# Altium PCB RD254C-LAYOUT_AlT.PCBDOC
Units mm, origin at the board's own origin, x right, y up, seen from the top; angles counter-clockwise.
Board outline 100 x 100 mm, 2 copper layers (TOP, BOTTOM), stack 0 mm thick; 40 components, 28 nets, 265 pads, 0 vias.
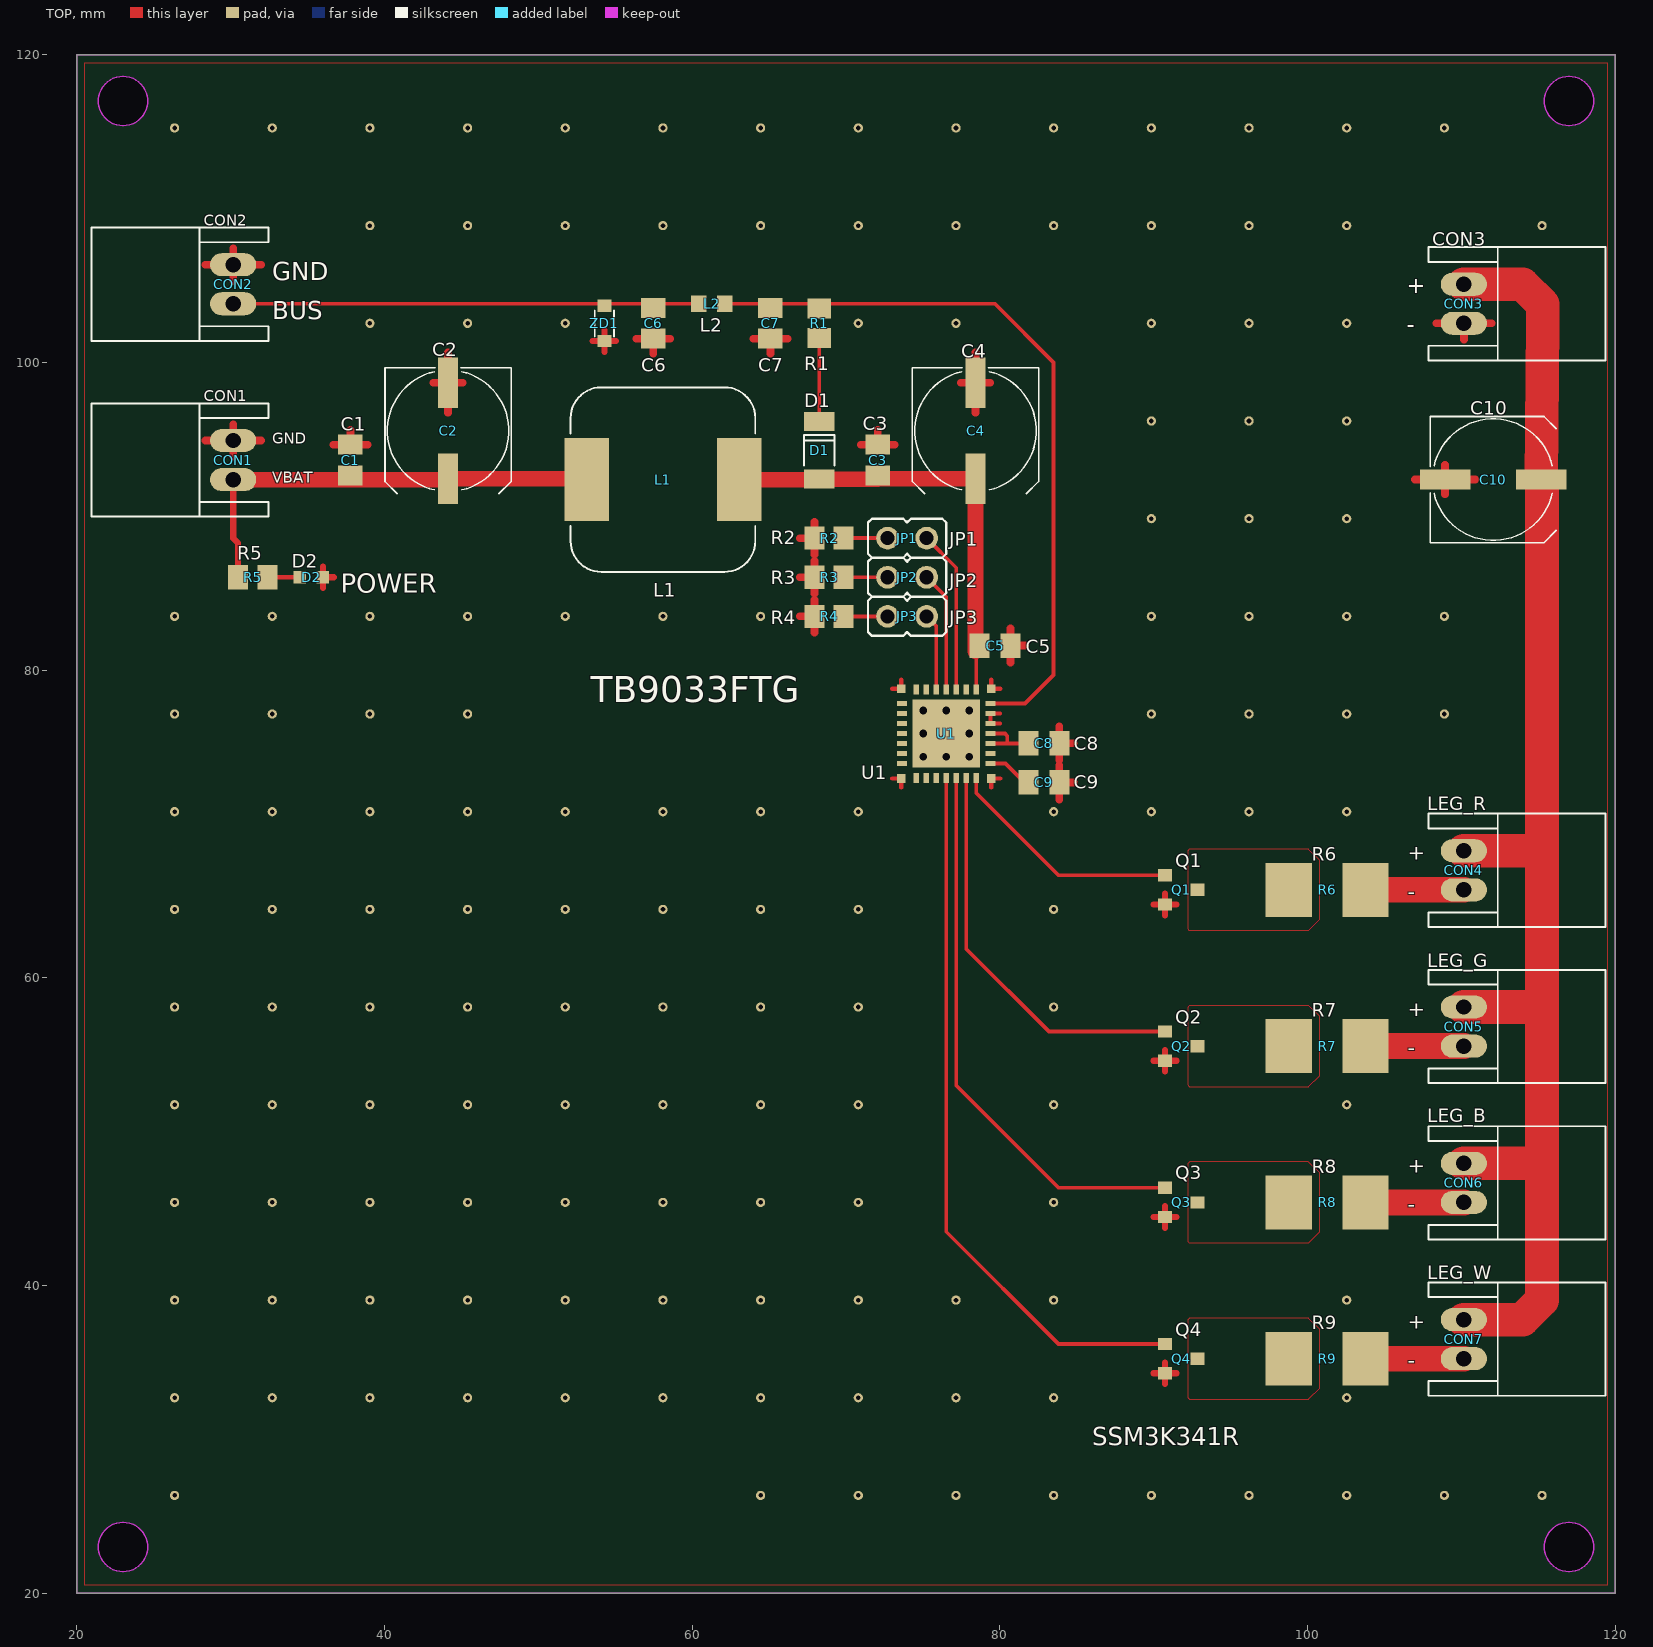
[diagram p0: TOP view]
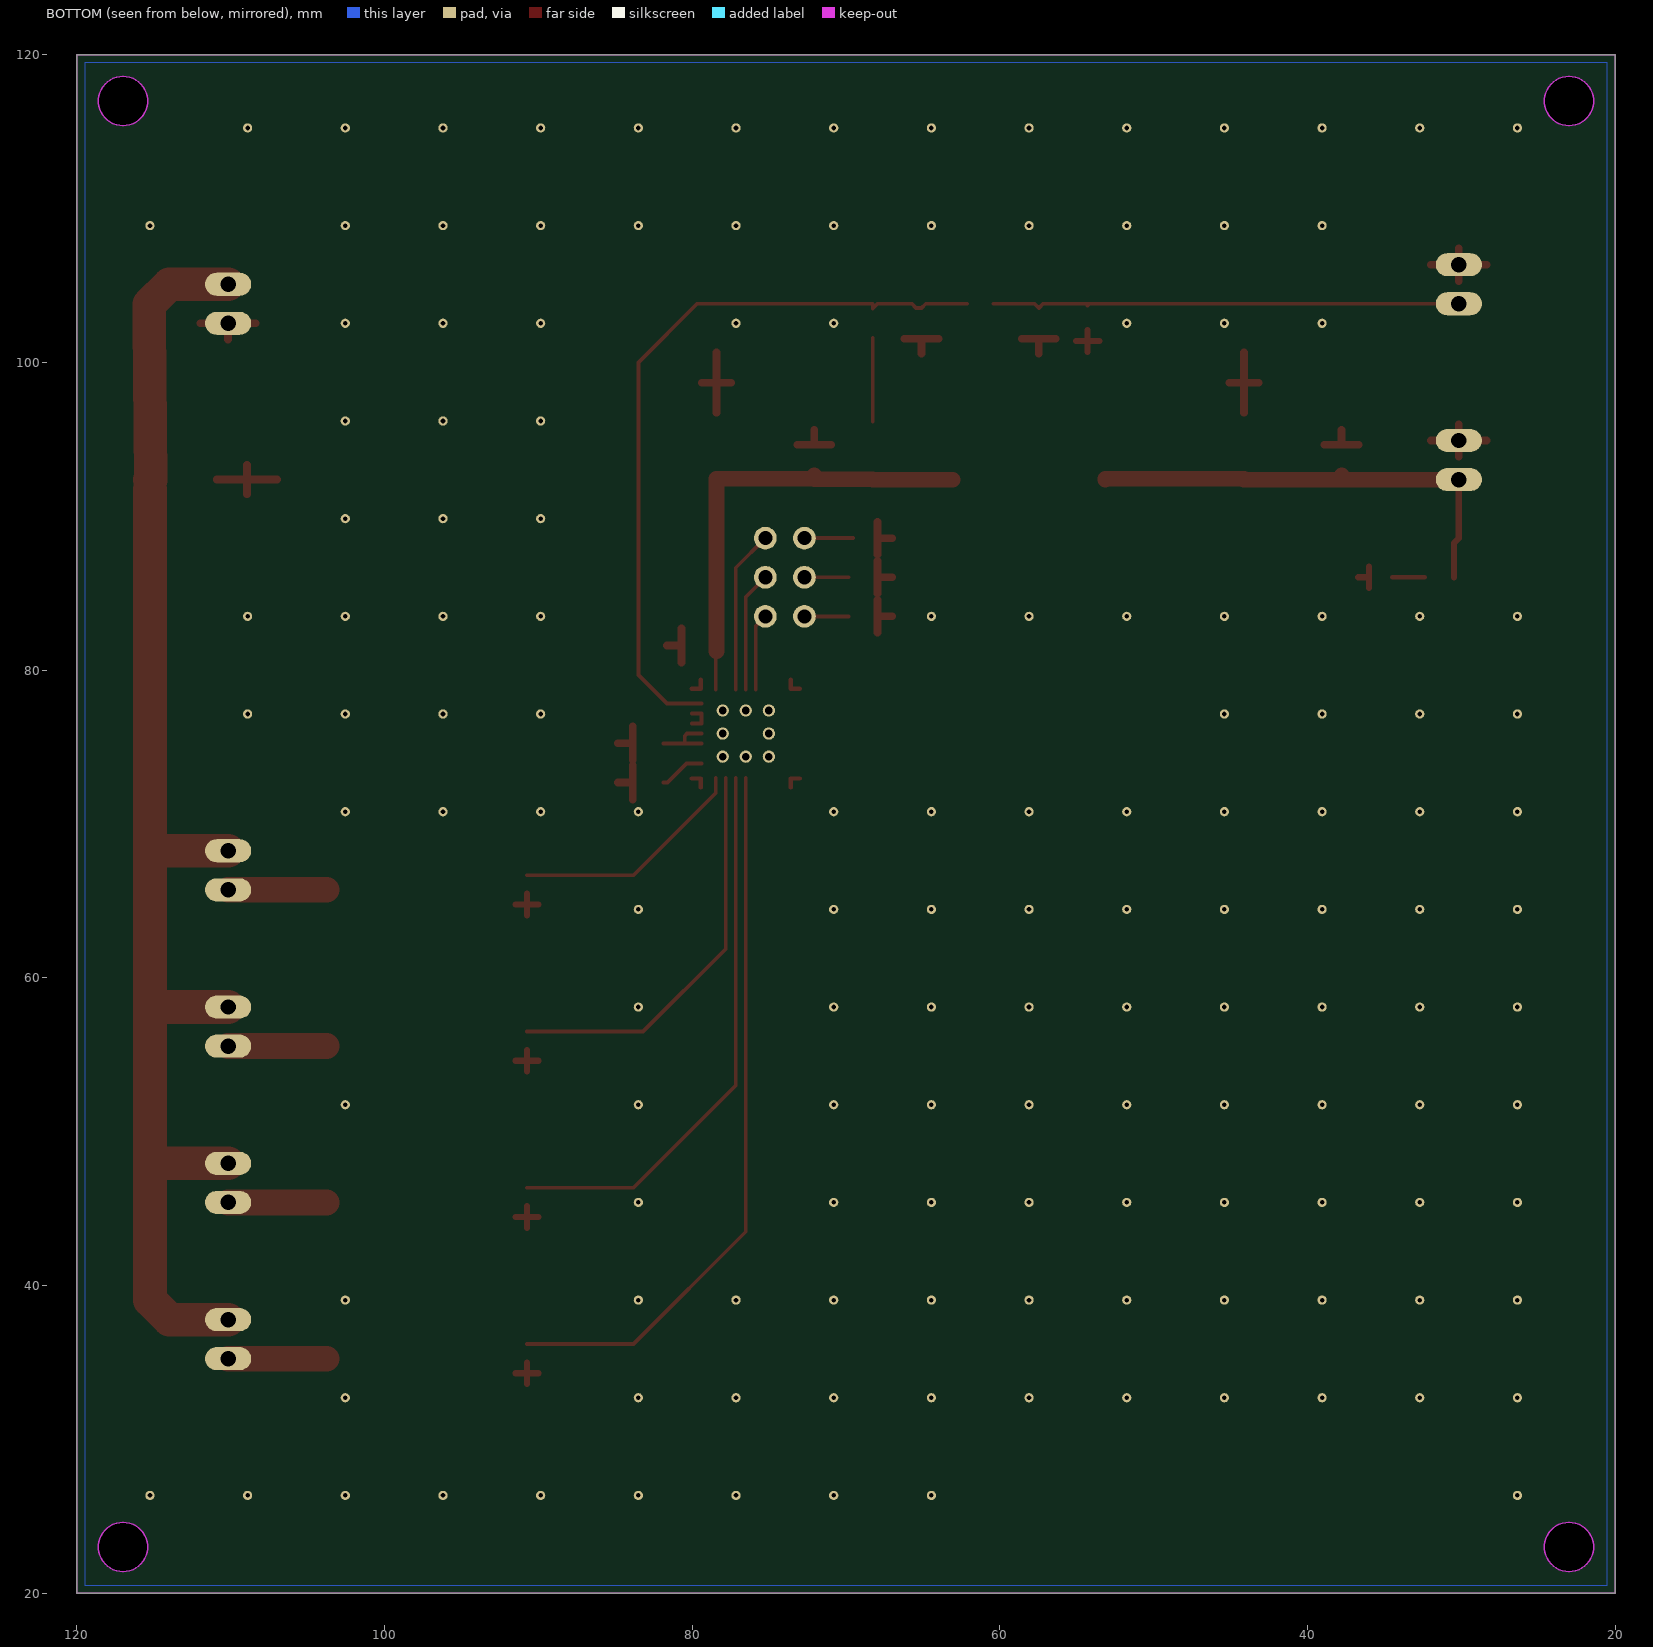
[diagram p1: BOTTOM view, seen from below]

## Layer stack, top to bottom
Top Solder: solder mask 0.0102, Solder Resist, Dk 3.5
TOP: signal copper (thickness not stored)
BOTTOM: signal copper (thickness not stored)
Bottom Solder: solder mask 0.0102, Solder Resist, Dk 3.5

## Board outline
20,20 20,120 120,120 120,20

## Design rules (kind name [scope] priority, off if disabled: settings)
AssemblyTestPointUsage [All] p0: scope1count=1 scope1_0_kind=Board scope1_0_value=Board scope2count=1 scope2_0_kind=Board scope2_0_value=Board commentlength=0
AssemblyTestpoint [All] p0: scope1count=1 scope1_0_kind=Board scope1_0_value=Board scope2count=1 scope2_0_kind=Board scope2_0_value=Board commentlength=0
Clearance [All] p0: scope1count=1 scope1_0_kind=Board scope1_0_value=Board scope2count=1 scope2_0_kind=Board scope2_0_value=Board commentlength=0 gap=0.254
Clearance [All] p1: gap=0.254 ignorepadtopadclearanceinfootprint=TRUE except(0: Arc-Arc Arc-Track Arc-Text Track-Track Track-Text Text-Text; 0.3: Arc-Hole Track-Hole SMDPad-Hole THPad-Hole Via-Hole Fill-Hole Poly-Hole Region-Hole Text-Hole)
ComponentClearance [All] p0: scope1count=1 scope1_0_kind=Board scope1_0_value=Board scope2count=1 scope2_0_kind=Board scope2_0_value=Board commentlength=0 gap=0.254 collisioncheckmode=3
DiffPairsRouting [All] p0: scope1count=1 scope1_0_kind=Board scope1_0_value=Board scope2count=1 scope2_0_kind=Board scope2_0_value=Board commentlength=0
FabricationTestPointUsage [All] p0: scope1count=1 scope1_0_kind=Board scope1_0_value=Board scope2count=1 scope2_0_kind=Board scope2_0_value=Board commentlength=0 valid=0 allowmultiple=FALSE
FabricationTestpoint [All] p0: scope1count=1 scope1_0_kind=Board scope1_0_value=Board scope2count=1 scope2_0_kind=Board scope2_0_value=Board commentlength=0 side=3 testpointundercomponent=TRUE minsize=1.016 maxsize=2.54 preferedsize=1.524 minholesize=0 maxholesize=1.016 preferedholesize=0.813 testpointgrid=0.025
FanoutControl Fanout_BGA [All] p0 off: scope1count=1 scope1_0_kind=Board scope1_0_value=Board scope2count=1 scope2_0_kind=Board scope2_0_value=Board commentlength=69 // Protel DXP Scope 1 Expression Was: IsBGA   Fanout_BGA (Default Rule)
FanoutControl Fanout_LCC [All] p0 off: scope1count=1 scope1_0_kind=Board scope1_0_value=Board scope2count=1 scope2_0_kind=Board scope2_0_value=Board commentlength=69 // Protel DXP Scope 1 Expression Was: IsLCC   Fanout_LCC (Default Rule)
FanoutControl Fanout_SOIC [All] p0 off: scope1count=1 scope1_0_kind=Board scope1_0_value=Board scope2count=1 scope2_0_kind=Board scope2_0_value=Board commentlength=71 // Protel DXP Scope 1 Expression Was: IsSOIC   Fanout_SOIC (Default Rule)
FanoutControl Fanout_Small [All] p0 off: scope1count=1 scope1_0_kind=Board scope1_0_value=Board scope2count=1 scope2_0_kind=Board scope2_0_value=Board commentlength=84 // Protel DXP Scope 1 Expression Was: (CompPinCount < 5)   Fanout_Small (Default Rule)
FanoutControl Fanout_Default [All] p0: scope1count=1 scope1_0_kind=Board scope1_0_value=Board scope2count=1 scope2_0_kind=Board scope2_0_value=Board commentlength=30 // Fanout_Default (Default Rule)
Height [All] p0: scope1count=1 scope1_0_kind=Board scope1_0_value=Board scope2count=1 scope2_0_kind=Board scope2_0_value=Board commentlength=0
HoleSize [All] p0: scope1count=1 scope1_0_kind=Board scope1_0_value=Board scope2count=1 scope2_0_kind=Board scope2_0_value=Board commentlength=0 absolutevalues=TRUE maxlimit=100 minlimit=0.001 maxpercent=80.000 minpercent=20.000
HoleSize [All] p1: absolutevalues=TRUE maxlimit=100 minlimit=0.001 maxpercent=80.000 minpercent=20.000
HoleToHoleClearance [All] p0: scope1count=1 scope1_0_kind=Board scope1_0_value=Board scope2count=1 scope2_0_kind=Board scope2_0_value=Board commentlength=0
HoleToHoleClearance [All] p1: gap=0.4 allowstackedmicrovias=FALSE
LayerPairs [All] p0: scope1count=1 scope1_0_kind=Board scope1_0_value=Board scope2count=1 scope2_0_kind=Board scope2_0_value=Board commentlength=0 enforce=TRUE
MinimumSolderMaskSliver [All] p0: scope1count=1 scope1_0_kind=Board scope1_0_value=Board scope2count=1 scope2_0_kind=Board scope2_0_value=Board commentlength=0
MinimumSolderMaskSliver [All] p1: minsoldermaskwidth=0.1
NetAntennae [All] p0: scope1count=1 scope1_0_kind=Board scope1_0_value=Board scope2count=1 scope2_0_kind=Board scope2_0_value=Board commentlength=0
NetAntennae [All] p1: netantennaetolerance=100
PasteMaskExpansion [All] p0: scope1count=1 scope1_0_kind=Board scope1_0_value=Board scope2count=1 scope2_0_kind=Board scope2_0_value=Board commentlength=0 expansion=0
PlaneClearance [All] p0: scope1count=1 scope1_0_kind=Board scope1_0_value=Board scope2count=1 scope2_0_kind=Board scope2_0_value=Board commentlength=0 clearance=0.001
PlaneClearance [All] p1: clearance=0.001
PlaneConnect [All] p0: scope1count=1 scope1_0_kind=Board scope1_0_value=Board scope2count=1 scope2_0_kind=Board scope2_0_value=Board commentlength=0 planeconnectstyle=Direct reliefexpansion=0.508 reliefentries=4 reliefconductorwidth=0.254 reliefairgap=0.254
PlaneConnect [All] p1: planeconnectstyle=Direct reliefexpansion=0.508 reliefentries=4 reliefconductorwidth=0.254 reliefairgap=0.254
PolygonConnect [All] p0: scope1count=1 scope1_0_kind=Board scope1_0_value=Board scope2count=1 scope2_0_kind=Board scope2_0_value=Board commentlength=0 connectstyle=Direct reliefconductorwidth=0.254 reliefentries=4 polygonreliefangle="90 Angle"
PolygonConnect [All] p1: connectstyle=Direct reliefconductorwidth=0.254 reliefentries=4 polygonreliefangle="90 Angle" airgapwidth=0.254
RoutingCorners [All] p0: scope1count=1 scope1_0_kind=Board scope1_0_value=Board scope2count=1 scope2_0_kind=Board scope2_0_value=Board commentlength=0 cornerstyle=45-Degree minsetback=2.54 maxsetback=2.54
RoutingLayers [All] p0: scope1count=1 scope1_0_kind=Board scope1_0_value=Board scope2count=1 scope2_0_kind=Board scope2_0_value=Board commentlength=0 top layer=Automatic bottom layer=Automatic
RoutingPriority [All] p0: scope1count=1 scope1_0_kind=Board scope1_0_value=Board scope2count=1 scope2_0_kind=Board scope2_0_value=Board commentlength=0
RoutingTopology [All] p0: scope1count=1 scope1_0_kind=Board scope1_0_value=Board scope2count=1 scope2_0_kind=Board scope2_0_value=Board commentlength=0 topology=Shortest
RoutingVias [All] p0: scope1count=1 scope1_0_kind=Board scope1_0_value=Board scope2count=1 scope2_0_kind=Board scope2_0_value=Board commentlength=0 holewidth=0.1 width=0.1 viastyle="Through Hole" minholewidth=0.001 minwidth=0.001 maxholewidth=100 maxwidth=100
RoutingVias [All] p1: holewidth=0.1 width=0.1 viastyle="Through Hole" minholewidth=0.001 minwidth=0.001 maxholewidth=100 maxwidth=100
ShortCircuit [All] p0: scope1count=1 scope1_0_kind=Board scope1_0_value=Board scope2count=1 scope2_0_kind=Board scope2_0_value=Board commentlength=0 allowed=FALSE
SilkToBoardRegionClearance [All] p0: scope1count=1 scope1_0_kind=Board scope1_0_value=Board scope2count=1 scope2_0_kind=Board scope2_0_value=Board commentlength=0
SilkToSilkClearance [All] p0: scope1count=1 scope1_0_kind=Board scope1_0_value=Board scope2count=1 scope2_0_kind=Board scope2_0_value=Board commentlength=0
SilkToSilkClearance [All] p1: silktosilkclearance=0.001
SilkToSolderMaskClearance [All] p0 off: scope1count=1 scope1_0_kind=Board scope1_0_value=Board scope2count=1 scope2_0_kind=Board scope2_0_value=Board commentlength=44 // Protel DXP Scope 1 Expression Was: IsPad
SilkToSolderMaskClearance [IsPad] p1: minsilkscreentomaskgap=0 clearancetoexposedcopper=TRUE
SolderMaskExpansion [All] p0: scope1count=1 scope1_0_kind=Board scope1_0_value=Board scope2count=1 scope2_0_kind=Board scope2_0_value=Board commentlength=0 expansion=0.001
SolderMaskExpansion [All] p1: expansion=0.001
UnRoutedNet [All] p0: scope1count=1 scope1_0_kind=Board scope1_0_value=Board scope2count=1 scope2_0_kind=Board scope2_0_value=Board commentlength=0
UnpouredPolygon [All] p0: scope1count=1 scope1_0_kind=Board scope1_0_value=Board scope2count=1 scope2_0_kind=Board scope2_0_value=Board commentlength=0
Width [All] p0: scope1count=1 scope1_0_kind=Board scope1_0_value=Board scope2count=1 scope2_0_kind=Board scope2_0_value=Board commentlength=0 maxlimit=1000 minlimit=2539.975 preferedwidth=0
Width [All] p1: maxlimit=1000 minlimit=2539.975 preferedwidth=0 toplayer_minwidth=0 bottomlayer_minwidth=0 minimp=50.000000 maximp=50.000000 favimp=50.000000
22 further rules are at their usual default settings.

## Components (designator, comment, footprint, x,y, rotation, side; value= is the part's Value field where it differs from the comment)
C1 "C0805K" C0805K 37.78,93.66 r90 top
C2 "UD-8X10_NICHICON_01" UD-8X10_NICHICON_01 44.13,95.565 r270 top
C3 "C0805K" C0805K 72.07,93.66 r90 top
C4 "UD-8X10_NICHICON_01" UD-8X10_NICHICON_01 78.42,95.565 r270 top
C5 "C0805K" C0805K 79.69,81.595 r0 top
C6 "C0805K" C0805K 57.465,102.55 r270 top
C7 "C0805K" C0805K 65.085,102.55 r270 top
C8 "C0805K" C0805K 82.865,75.245 r180 top
C9 "C0805K" C0805K 82.865,72.705 r180 top
C10 "UD-8X10_NICHICON_01" UD-8X10_NICHICON_01 112.075,92.39 r0 top
cam1 "A4L-LOC" A4L-LOC -51,-27 r0 top
CON1 "S2B-XH-A" S2B-XH-A 30.16,93.66 r90 top
CON2 "S2B-XH-A" S2B-XH-A 30.16,105.09 r90 top
CON3 "S2B-XH-A" S2B-XH-A 110.17,103.82 r270 top
CON4 "S2B-XH-A" S2B-XH-A 110.17,66.99 r270 top
CON5 "S2B-XH-A" S2B-XH-A 110.17,56.83 r270 top
CON6 "S2B-XH-A" S2B-XH-A 110.17,46.67 r270 top
CON7 "S2B-XH-A" S2B-XH-A 110.17,36.51 r270 top
D1 "LL4148" LL4148 68.26,94.295 r90 top
D2 "CHIP-LED0603" CHIP-LED0603 35.24,86.04 r270 top
JP1 "JP1" JP1 73.975,88.58 r270 top
JP2 "JP1" JP1 73.975,86.04 r270 top
JP3 "JP1" JP1 73.975,83.5 r270 top
L1 "7447709222" 7447709222 58.1,92.39 r270 top
L2 "R0603" R0603 61.275,103.82 r0 top
Q1 "SOT-23F" SOT-23F 92.39,65.72 r270 top
Q2 "SOT-23F" SOT-23F 92.39,55.56 r270 top
Q3 "SOT-23F" SOT-23F 92.39,45.4 r270 top
Q4 "SOT-23F" SOT-23F 92.39,35.24 r270 top
R1 "R0805" R0805 68.26,102.55 r270 top
R2 "R0805" R0805 68.895,88.58 r180 top
R3 "R0805" R0805 68.895,86.04 r180 top
R4 "R0805" R0805 68.895,83.5 r180 top
R5 "M0805" M0805 31.43,86.04 r180 top
R6 "R2512-2010" R2512-2010 101.28,65.72 r0 top
R7 "R2512-2010" R2512-2010 101.28,55.56 r0 top
R8 "R2512-2010" R2512-2010 101.28,45.4 r0 top
R9 "R2512-2010" R2512-2010 101.28,35.24 r0 top
U1 "P-VQFN28-0606-0_65-003_01" P-VQFN28-0606-0_65-003_01 76.515,75.88 r180 top
ZD1 "USC" USC 54.29,102.55 r270 top

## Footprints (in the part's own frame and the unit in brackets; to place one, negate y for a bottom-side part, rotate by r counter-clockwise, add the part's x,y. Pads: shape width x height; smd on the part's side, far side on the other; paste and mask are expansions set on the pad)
7447709222 [mm] "KC00080BKP"
  rect 5.4x2.9 smd paste-5.603 mask+0: 1(0,-4.95) 2(0,4.95)
  silkscreen extent -6,-6 6,6
A4L-LOC [mm] "KC00080BKP"
C0805K [mm] "KC00080BKP"
  rect 1.3x1.6 smd paste-1.803 mask+0: 1(-1,0) 2(1,0)
CHIP-LED0603 [mm] "KC00080BKP"
  rect 0.8x0.8 smd paste-1.003 mask+0: A(0,-0.75) C(0,0.75)
JP1 [mm] "KC00080BKP"
  round 1.48 / inner round 0 / far side round 1.48 hole 0.914 paste-1.68 mask+0: 1(0,-1.27) 2(0,1.27)
  silkscreen extent -1.27,-2.54 1.27,2.54
LL4148 [mm] "KC00080BKP"
  rect 1.25x2 smd paste-2.203 mask+0: A(-1.875,0) K(1.875,0)
  silkscreen extent -1,-1 1,1
M0805 [mm] "KC00080BKP"
  rect 1.3x1.6 smd paste-1.803 mask+0: 1(-0.95,0) 2(0.95,0)
P-VQFN28-0606-0_65-003_01 [mm] "KC00080BKP"
  rect 0.35x0.65 smd paste-0.853 mask+0: 1(-1.95,-2.875) 2(-1.3,-2.875) 3(-0.65,-2.875) 4(0,-2.875) 5(0.65,-2.875) 6(1.3,-2.875) 7(1.95,-2.875) 15(1.95,2.875) 16(1.3,2.875) 17(0.65,2.875) 18(0,2.875) 19(-0.65,2.875) 20(-1.3,2.875) 21(-1.95,2.875)
  rect 0.56x0.56 smd paste-0.763 mask+0: 1T(-2.92,-2.92) 2T(2.92,-2.92) 3T(2.92,2.92) 4T(-2.92,2.92)
  rect 0.65x0.35 smd paste-0.853 mask+0: 8(2.875,-1.95) 9(2.875,-1.3) 10(2.875,-0.65) 11(2.875,0) 12(2.875,0.65) 13(2.875,1.3) 14(2.875,1.95) 22(-2.875,1.95) 23(-2.875,1.3) 24(-2.875,0.65) 25(-2.875,0) 26(-2.875,-0.65) 27(-2.875,-1.3) 28(-2.875,-1.95)
  rect 4.4x4.4 smd paste-4.603 mask+0: E_PAD(0,0)
  round 0.8 / inner round 0 / far side round 0.8 hole 0.5 paste-1.05 mask+0: ""(-1.5,1.5) ""(-1.5,0) ""(-1.5,-1.5) ""(0,1.5) ""(0,-1.5) ""(1.5,1.5) ""(1.5,0) ""(1.5,-1.5)
R0603 [mm] "KC00080BKP"
  rect 1x1.1 smd paste-1.303 mask+0: 1(-0.85,0) 2(0.85,0)
R0805 [mm] "KC00080BKP"
  rect 1.3x1.5 smd paste-1.703 mask+0: 1(-0.95,0) 2(0.95,0)
R2512-2010 [mm] "KC00080BKP"
  rect 3x3.5 smd paste-3.703 mask+0: P_1(-2.5,0) P_2(2.5,0)
S2B-XH-A [mm] "KC00080BKP"
  oval 1.5x3 / inner round 0 / far side oval 1.5x3 hole 1 paste-3.203 mask+0: 1(1.27,0) 2(-1.27,0)
  silkscreen extent -3.68,-2.3 3.68,9.2
SOT-23F [mm] "KC00080BKP"
  rect 0.8x0.9 smd paste-1.103 mask+0: 1(-0.95,-1.65) 2(0.95,-1.65) 3(0,0.45)
UD-8X10_NICHICON_01 [mm] "KC00080BKP"
  rect 3.3x1.3 smd paste-3.503 mask+0: 1(-3.125,0) 2(3.125,0)
  silkscreen extent -4.1,-4.1 4.1,4.1
USC [mm] "KC00080BKP"
  rect 0.8x0.9 smd paste-1.103 mask+0: 1(-1.15,0) 2(1.15,0)
  silkscreen extent -0.85,-0.63 0.85,0.63

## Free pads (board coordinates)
  round 0 hole 3.2 unplated paste-3.4 mask+0: ""(23,23) ""(23,117) ""(117,23) ""(117,117)
  round 0.6 / inner round 0 / far side round 0.6 hole 0.3 paste-0.6 mask+0: ""(26.35,26.35) ""(26.35,32.7) ""(26.35,39.05) ""(26.35,45.4) ""(26.35,51.75) ""(26.35,58.1) ""(26.35,64.45) ""(26.35,70.8) ""(26.35,77.15) ""(26.35,83.5) ""(26.35,115.25) ""(32.7,32.7) ""(32.7,39.05) ""(32.7,45.4) ""(32.7,51.75) ""(32.7,58.1) ""(32.7,64.45) ""(32.7,70.8) ""(32.7,77.15) ""(32.7,83.5) ""(32.7,115.25) ""(39.05,32.7) ""(39.05,39.05) ""(39.05,45.4) ""(39.05,51.75) ""(39.05,58.1) ""(39.05,64.45) ""(39.05,70.8) ""(39.05,77.15) ""(39.05,83.5) ""(39.05,102.55) ""(39.05,108.9) ""(39.05,115.25) ""(45.4,32.7) ""(45.4,39.05) ""(45.4,45.4) ""(45.4,51.75) ""(45.4,58.1) ""(45.4,64.45) ""(45.4,70.8) ""(45.4,77.15) ""(45.4,83.5) ""(45.4,102.55) ""(45.4,108.9) ""(45.4,115.25) ""(51.75,32.7) ""(51.75,39.05) ""(51.75,45.4) ""(51.75,51.75) ""(51.75,58.1) ""(51.75,64.45) ""(51.75,70.8) ""(51.75,83.5) ""(51.75,102.55) ""(51.75,108.9) ""(51.75,115.25) ""(58.1,32.7) ""(58.1,39.05) ""(58.1,45.4) ""(58.1,51.75) ""(58.1,58.1) ""(58.1,64.45) ""(58.1,70.8) ""(58.1,83.5) ""(58.1,108.9) ""(58.1,115.25) ""(64.45,26.35) ""(64.45,32.7) ""(64.45,39.05) ""(64.45,45.4) ""(64.45,51.75) ""(64.45,58.1) ""(64.45,64.45) ""(64.45,70.8) ""(64.45,83.5) ""(64.45,108.9) ""(64.45,115.25) ""(70.8,26.35) ""(70.8,32.7) ""(70.8,39.05) ""(70.8,45.4) ""(70.8,51.75) ""(70.8,58.1) ""(70.8,64.45) ""(70.8,70.8) ""(70.8,102.55) ""(70.8,108.9) ""(70.8,115.25) ""(77.15,26.35) ""(77.15,32.7) ""(77.15,39.05) ""(77.15,102.55) ""(77.15,108.9) ""(77.15,115.25) ""(83.5,26.35) ""(83.5,32.7) ""(83.5,39.05) ""(83.5,45.4) ""(83.5,51.75) ""(83.5,58.1) ""(83.5,64.45) ""(83.5,70.8) ""(83.5,108.9) ""(83.5,115.25) ""(89.85,26.35) ""(89.85,70.8) ""(89.85,77.15) ""(89.85,83.5) ""(89.85,89.85) ""(89.85,96.2) ""(89.85,102.55) ""(89.85,108.9) ""(89.85,115.25) ""(96.2,26.35) ""(96.2,70.8) ""(96.2,77.15) ""(96.2,83.5) ""(96.2,89.85) ""(96.2,96.2) ""(96.2,102.55) ""(96.2,108.9) ""(96.2,115.25) ""(102.55,26.35) ""(102.55,32.7) ""(102.55,39.05) ""(102.55,51.75) ""(102.55,70.8) ""(102.55,77.15) ""(102.55,83.5) ""(102.55,89.85) ""(102.55,96.2) ""(102.55,102.55) ""(102.55,108.9) ""(102.55,115.25) ""(108.9,26.35) ""(108.9,77.15) ""(108.9,83.5) ""(108.9,115.25) ""(115.25,26.35) ""(115.25,108.9)

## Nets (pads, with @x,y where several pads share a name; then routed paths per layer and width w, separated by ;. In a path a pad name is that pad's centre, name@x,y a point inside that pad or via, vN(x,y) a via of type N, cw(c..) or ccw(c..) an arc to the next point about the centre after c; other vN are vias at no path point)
+12V: C1.1 C2.2 CON1.2 L1.1 R5.2 | length 29.8
  TOP w0.406: CON1.2 30.16,88.58 30.48,88.26 R5.2
  TOP w1.016: CON1.2 C1.1@37.78,92.39 ; C1.1 C1.1@37.78,92.39 ; L1.1 53.15,92.44 C2.2 44.13,92.39 C1.1@37.78,92.39
BUS: C7.1 L2.2 R1.1 U1.28 | length 48.8
  TOP w0.254: L2.2 64.815,103.82 C7.1 65.45,103.55 65.72,103.82 67.94,103.82 R1.1 68.26,103.82 79.69,103.82 83.5,100.01 83.5,79.69 81.64,77.83 U1.28
GND: C1.2 C2.1 C3.2 C4.1 C5.2 C6.2 C7.2 C8.1 C9.1 C10.1 CON1.1 CON2.1 CON3.1 D2.C pad.@26.35,26.35 pad.@26.35,32.7 pad.@26.35,39.05 pad.@26.35,45.4 pad.@26.35,51.75 pad.@26.35,58.1 pad.@26.35,64.45 pad.@26.35,70.8 pad.@26.35,77.15 pad.@26.35,83.5 pad.@26.35,115.25 pad.@32.7,32.7 pad.@32.7,39.05 pad.@32.7,45.4 pad.@32.7,51.75 pad.@32.7,58.1 pad.@32.7,64.45 pad.@32.7,70.8 pad.@32.7,77.15 pad.@32.7,83.5 pad.@32.7,115.25 pad.@39.05,32.7 pad.@39.05,39.05 pad.@39.05,45.4 pad.@39.05,51.75 pad.@39.05,58.1 pad.@39.05,64.45 pad.@39.05,70.8 pad.@39.05,77.15 pad.@39.05,83.5 pad.@39.05,102.55 pad.@39.05,108.9 pad.@39.05,115.25 pad.@45.4,32.7 pad.@45.4,39.05 pad.@45.4,45.4 pad.@45.4,51.75 pad.@45.4,58.1 pad.@45.4,64.45 pad.@45.4,70.8 pad.@45.4,77.15 pad.@45.4,83.5 pad.@45.4,102.55 pad.@45.4,108.9 pad.@45.4,115.25 pad.@51.75,32.7 pad.@51.75,39.05 pad.@51.75,45.4 pad.@51.75,51.75 pad.@51.75,58.1 pad.@51.75,64.45 pad.@51.75,70.8 pad.@51.75,83.5 pad.@51.75,102.55 pad.@51.75,108.9 pad.@51.75,115.25 pad.@58.1,32.7 pad.@58.1,39.05 pad.@58.1,45.4 pad.@58.1,51.75 pad.@58.1,58.1 pad.@58.1,64.45 pad.@58.1,70.8 pad.@58.1,83.5 pad.@58.1,108.9 pad.@58.1,115.25 pad.@64.45,26.35 pad.@64.45,32.7 pad.@64.45,39.05 pad.@64.45,45.4 pad.@64.45,51.75 pad.@64.45,58.1 pad.@64.45,64.45 pad.@64.45,70.8 pad.@64.45,83.5 pad.@64.45,108.9 pad.@64.45,115.25 pad.@70.8,26.35 pad.@70.8,32.7 pad.@70.8,39.05 pad.@70.8,45.4 pad.@70.8,51.75 pad.@70.8,58.1 pad.@70.8,64.45 pad.@70.8,70.8 pad.@70.8,102.55 pad.@70.8,108.9 pad.@70.8,115.25 pad.@77.15,26.35 pad.@77.15,32.7 pad.@77.15,39.05 pad.@77.15,102.55 pad.@77.15,108.9 pad.@77.15,115.25 pad.@83.5,26.35 pad.@83.5,32.7 pad.@83.5,39.05 pad.@83.5,45.4 pad.@83.5,51.75 pad.@83.5,58.1 pad.@83.5,64.45 pad.@83.5,70.8 pad.@83.5,108.9 pad.@83.5,115.25 pad.@89.85,26.35 pad.@89.85,70.8 pad.@89.85,77.15 pad.@89.85,83.5 pad.@89.85,89.85 pad.@89.85,96.2 pad.@89.85,102.55 pad.@89.85,108.9 pad.@89.85,115.25 pad.@96.2,26.35 pad.@96.2,70.8 pad.@96.2,77.15 pad.@96.2,83.5 pad.@96.2,89.85 pad.@96.2,96.2 pad.@96.2,102.55 pad.@96.2,108.9 pad.@96.2,115.25 pad.@102.55,26.35 pad.@102.55,32.7 pad.@102.55,39.05 pad.@102.55,51.75 pad.@102.55,70.8 pad.@102.55,77.15 pad.@102.55,83.5 pad.@102.55,89.85 pad.@102.55,96.2 pad.@102.55,102.55 pad.@102.55,108.9 pad.@102.55,115.25 pad.@108.9,26.35 pad.@108.9,77.15 pad.@108.9,83.5 pad.@108.9,115.25 pad.@115.25,26.35 pad.@115.25,108.9 Q1.2 Q2.2 Q3.2 Q4.2 R2.2 R3.2 R4.2 U1. U1.1T U1.2T U1.3T U1.4T U1.26 U1.27 U1.E_PAD ZD1.2 | length 88.2
  TOP w0.254: 80.02,76.53 U1.26 U1.27 80.02,77.18
  TOP w0.28: 73.01,72.96 U1.3T 73.595,72.375 ; 73.01,78.8 U1.2T 73.595,79.385 ; 79.435,72.375 U1.4T 80.02,72.96 ; 79.435,79.385 U1.1T 80.02,78.8
  TOP w0.4: 35.99,85.335 D2.C ; 35.99,86.745 D2.C ; 36.695,86.04 D2.C ; 53.535,101.4 ZD1.2 ; 54.29,100.695 ZD1.2 ; 54.29,102.105 ZD1.2 ; 55.045,101.4 ZD1.2 ; 89.985,34.29 Q4.2 ; 89.985,44.45 Q3.2 ; 89.985,54.61 Q2.2 ; 89.985,64.77 Q1.2 ; 90.74,33.585 Q4.2 ; 90.74,34.995 Q4.2 ; 90.74,43.745 Q3.2 ; 90.74,45.155 Q3.2 ; 90.74,53.905 Q2.2 ; 90.74,55.315 Q2.2 ; 90.74,64.065 Q1.2 ; 90.74,65.475 Q1.2 ; 91.495,34.29 Q4.2 ; 91.495,44.45 Q3.2 ; 91.495,54.61 Q2.2 ; 91.495,64.77 Q1.2
  TOP w0.5: 28.355,94.93 CON1.1 ; 28.355,106.36 CON2.1 ; 30.16,93.875 CON1.1 ; 30.16,95.985 CON1.1 ; 30.16,105.305 CON2.1 ; 30.16,107.415 CON2.1 ; 31.965,94.93 CON1.1 ; 31.965,106.36 CON2.1 ; 108.365,102.55 CON3.1 ; 110.17,101.495 CON3.1 ; 111.975,102.55 CON3.1
  TOP w0.508: 36.675,94.66 C1.2 ; 37.78,95.615 C1.2 ; 38.885,94.66 C1.2 ; 43.175,98.69 C2.1 ; 44.13,96.735 C2.1 ; 44.13,100.645 C2.1 ; 45.085,98.69 C2.1 ; 56.36,101.55 C6.2 ; 57.465,100.595 C6.2 ; 58.57,101.55 C6.2 ; 63.98,101.55 C7.2 ; 65.085,100.595 C7.2 ; 66.19,101.55 C7.2 ; 66.99,83.5 R4.2 ; 66.99,86.04 R3.2 ; 66.99,88.58 R2.2 ; 67.945,82.445 R4.2 ; 67.945,84.555 R4.2 ; 67.945,84.985 R3.2 ; 67.945,87.095 R3.2 ; 67.945,87.525 R2.2 ; 67.945,89.635 R2.2 ; 70.965,94.66 C3.2 ; 72.07,95.615 C3.2 ; 73.175,94.66 C3.2 ; 77.465,98.69 C4.1 ; 78.42,96.735 C4.1 ; 78.42,100.645 C4.1 ; 79.375,98.69 C4.1 ; 80.69,80.49 C5.2 ; 80.69,82.7 C5.2 ; 81.645,81.595 C5.2 ; 83.865,71.6 C9.1 ; 83.865,73.81 C9.1 ; 83.865,74.14 C8.1 ; 83.865,76.35 C8.1 ; 84.82,72.705 C9.1 ; 84.82,75.245 C8.1 ; 106.995,92.39 C10.1 ; 108.95,91.435 C10.1 ; 108.95,93.345 C10.1 ; 110.905,92.39 C10.1
N_1: D1.K R1.2 | length 5.4
  TOP w0.254: D1.K R1.2
N_2: JP1.1 R2.1 | length 3.2
  TOP w0.254: R2.1@69.53,88.58 R2.1 JP1.1
N_3: JP2.1 R3.1 | length 2.9
  TOP w0.254: R3.1 JP2.1
N_4: JP3.1 R4.1 | length 2.9
  TOP w0.254: R4.1 JP3.1
N_5: C10.2 CON3.2 CON4.2 CON5.2 CON6.2 CON7.2 | length 91.4
  TOP w0.406: C10.2 115.225,92.365 115.25,92.34 C10.2@115.25,91.755
  TOP w2.184: CON7.2 113.98,37.78 115.25,39.05 115.25,47.94 ; CON6.2 115.25,47.94 ; CON5.2 115.25,58.1 ; CON4.2 115.25,68.26 ; CON3.2 113.98,105.09 115.3,103.77 115.3,102.55 C10.2 115.2,92.34 115.225,92.365 C10.2@115.25,92.39 ; C10.2@115.25,91.755 115.25,68.26 ; 115.25,47.94 115.25,58.1 ; 115.25,58.1 115.25,68.26
N_6: CON4.1 R6.P_2 | length 6.4
  TOP w1.676: R6.P_2 CON4.1
N_7: CON5.1 R7.P_2 | length 6.4
  TOP w1.676: R7.P_2 CON5.1
N_8: CON6.1 R8.P_2 | length 6.4
  TOP w1.676: R8.P_2 CON6.1
N_9: CON7.1 R9.P_2 | length 6.4
  TOP w1.676: R9.P_2 CON7.1
N_10: Q1.3 R6.P_1
N_11: Q2.3 R7.P_1
N_12: Q3.3 R8.P_1
N_13: Q4.3 R9.P_1
N_14: Q1.1 U1.21 | length 15.5
  TOP w0.254: U1.21 78.465,72.025 83.82,66.67 Q1.1
N_15: Q2.1 U1.20 | length 26.3
  TOP w0.254: U1.20 77.815,61.88 83.185,56.51 Q2.1
N_16: Q3.1 U1.19 | length 36.3
  TOP w0.254: U1.19 77.165,53.005 83.82,46.35 Q3.1
N_17: Q4.1 U1.18 | length 46.8
  TOP w0.254: U1.18 76.515,43.495 83.82,36.19 Q4.1
N_18: JP3.2 U1.5 | length 5
  TOP w0.254: JP3.2 75.865,82.88 U1.5
N_19: JP2.2 U1.4 | length 7.8
  TOP w0.254: JP2.2 76.515,84.77 U1.4
N_20: JP1.2 U1.3 | length 10.6
  TOP w0.254: JP1.2 77.165,86.66 U1.3
N_30: D2.A R5.1 | length 2.1
  TOP w0.305: R5.1 D2.A
N_41: C6.1 CON2.2 L2.1 ZD1.1 | length 30.7
  TOP w0.254: CON2.2 54.17,103.82 ZD1.1 54.29,103.82 57.195,103.82 C6.1 57.735,103.82 L2.1
VBAT: C3.1 C4.2 C5.1 D1.A L1.2 U1.1 | length 30.2
  TOP w0.254: C5.1@78.42,81.23 C5.1 78.465,80.735 U1.1
  TOP w1.016: L1.2 68.26,92.39 D1.A 72.07,92.42 C3.1@72.07,92.44 ; C3.1 C3.1@72.07,92.44 ; C5.1@78.42,81.23 C4.2 C3.1@72.07,92.44
VCC: C8.2 U1.24 U1.25 | length 4.1
  TOP w0.254: U1.24 80.484,75.23 ; U1.25 80.325,75.88 80.484,75.721 80.484,75.23 ; C8.2 81.85,75.23 80.484,75.23
VDD: C9.2 U1.22 | length 3
  TOP w0.254: U1.22 80.37,73.93 81.595,72.705 C9.2
pads on no net: U1.2 U1.6 U1.7 U1.8 U1.9 U1.10 U1.11 U1.12 U1.13 U1.14 U1.15 U1.16 U1.17 U1.23

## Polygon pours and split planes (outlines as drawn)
GND on TOP "TOP5" (solid, pour order 7): 20.575,20.5 cw(c20.575,20.575) 20.5,20.575 20.5,119.425 cw(c20.575,119.425) 20.575,119.5 119.425,119.5 cw(c119.425,119.425) 119.5,119.425 119.5,20.575 cw(c119.425,20.575) 119.425,20.5
N_10 on TOP "TOP1" (solid, pour order 3): 92.369,63.053 cw(c92.369,63.128) 92.316,63.075 92.285,63.106 cw(c92.338,63.159) 92.263,63.159 92.263,68.276 cw(c92.338,68.276) 92.285,68.329 92.321,68.365 cw(c92.374,68.312) 92.374,68.387 100.006,68.387 cw(c100.006,68.312) 100.059,68.365 100.75,67.674 cw(c100.697,67.621) 100.772,67.621 100.772,63.813 cw(c100.697,63.813) 100.75,63.76 100.065,63.075 cw(c100.012,63.128) 100.012,63.053
N_11 on TOP "TOP2" (solid, pour order 4): 92.389,52.893 cw(c92.389,52.968) 92.336,52.915 92.285,52.966 cw(c92.338,53.019) 92.263,53.019 92.263,58.105 cw(c92.338,58.105) 92.285,58.159 92.331,58.205 cw(c92.384,58.152) 92.384,58.227 100.013,58.227 cw(c100.013,58.152) 100.066,58.205 100.75,57.521 cw(c100.697,57.468) 100.772,57.468 100.772,53.655 cw(c100.697,53.655) 100.75,53.602 100.063,52.915 cw(c100.01,52.968) 100.01,52.893
N_12 on TOP "TOP3" (solid, pour order 5): 92.377,42.733 cw(c92.377,42.808) 92.324,42.755 92.285,42.794 cw(c92.338,42.847) 92.263,42.847 92.263,47.94 cw(c92.338,47.94) 92.285,47.993 92.337,48.045 cw(c92.39,47.992) 92.39,48.067 100.009,48.067 cw(c100.009,47.992) 100.062,48.045 100.75,47.357 cw(c100.697,47.304) 100.772,47.304 100.772,43.499 cw(c100.697,43.499) 100.75,43.446 100.059,42.755 cw(c100.006,42.808) 100.006,42.733
N_13 on TOP "TOP4" (solid, pour order 6): 92.376,32.573 cw(c92.376,32.648) 92.323,32.595 92.285,32.633 cw(c92.338,32.686) 92.263,32.686 92.263,37.783 cw(c92.338,37.783) 92.285,37.836 92.334,37.885 cw(c92.387,37.832) 92.387,37.907 100.007,37.907 cw(c100.007,37.832) 100.06,37.885 100.75,37.195 cw(c100.697,37.142) 100.772,37.142 100.772,33.335 cw(c100.697,33.335) 100.75,33.282 100.063,32.595 cw(c100.01,32.648) 100.01,32.573
GND on BOTTOM "BOTTOM6" (solid, pour order 2): 20.575,20.5 cw(c20.575,20.575) 20.5,20.575 20.5,119.425 cw(c20.575,119.425) 20.575,119.5 119.425,119.5 cw(c119.425,119.425) 119.5,119.425 119.5,20.575 cw(c119.425,20.575) 119.425,20.5

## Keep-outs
Keep-Out Layer:
  lines w0.1: 20,20 120,20 120,120 20,120 20,20 ; 23,21.4 cw(c23,23) 23,24.6 cw(c23,23) 23,21.4 ; 23,115.4 cw(c23,117) 23,118.6 cw(c23,117) 23,115.4 ; 117,21.4 cw(c117,23) 117,24.6 cw(c117,23) 117,21.4 ; 117,115.4 cw(c117,117) 117,118.6 cw(c117,117) 117,115.4

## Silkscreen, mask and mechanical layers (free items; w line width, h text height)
Top Overlay:
  text "GND" at 32.7,105.36 h1.17
  text "+" at 106.45,104.49 h1.07
  text "BUS" at 32.7,102.82 h1.17
  text "-" at 106.45,101.95 h1.07
  text "GND" at 32.7,94.73 h0.71
  text "VBAT" at 32.7,92.19 h0.71
  text "POWER" at 37.145,85.04 h1.24
  text "TB9033FTG" at 53.41,77.9 h1.7
  text "LEG_R" at 107.8,70.9 h0.89
  text "+" at 106.522,67.66 h0.99
  text "-" at 106.522,65.12 h0.99
  text "LEG_G" at 107.8,60.7 h0.89
  text "+" at 106.522,57.5 h0.99
  text "-" at 106.522,54.96 h0.99
  text "LEG_B" at 107.8,50.6 h0.89
  text "+" at 106.522,47.34 h0.99
  text "-" at 106.522,44.8 h0.99
  text "LEG_W" at 107.8,40.4 h0.89
  text "+" at 106.522,37.18 h0.99
  text "-" at 106.522,34.64 h0.99
  text "SSM3K341R" at 86,29.6 h1.17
